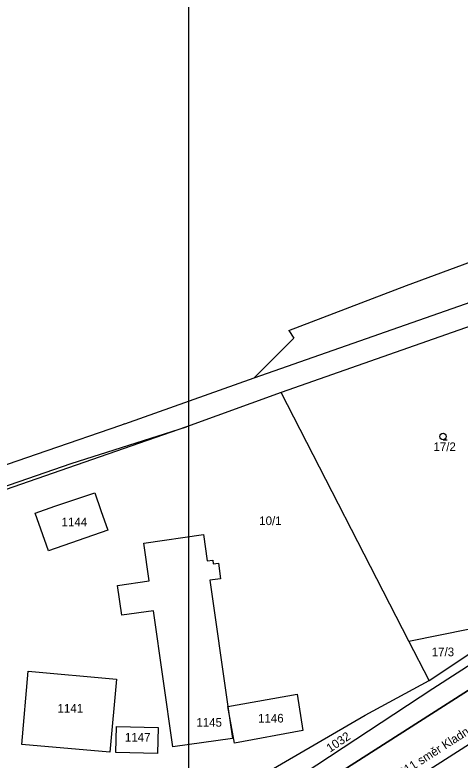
# Model space of a CAD drawing. Extents: x -752184 to -751416, y -1028299 to -1027836.
# Drawn here: x -751921.2 to -751817.9, y -1028131.4 to -1027958.6 of the extents above; entities that cross this region are included whole.
import ezdxf

# ---------------------------------------------------------------- set-up
doc = ezdxf.new("R2010")
doc.units = 0
for name, color, linetype in [('02_Osa_koleje', 7, 'Continuous'), ('Vrstva 4', 7, 'Continuous'), ('Vrstva 53', 7, 'Continuous'), ('Vrstva 55', 7, 'Continuous'), ('Vrstva 57', 7, 'Continuous'), ('Vrstva 58', 7, 'Continuous'), ('Vrstva 63', 7, 'Continuous')]:
    doc.layers.add(name, color=color, linetype=linetype)

msp = doc.modelspace()

# ---------------------------------------------------------------- linework, layer by layer
at = {"layer": 'Vrstva 4'}
msp.add_lwpolyline([(-751880.79, -1027897.6), (-751466.79, -1027897.6), (-751466.79, -1028188.6), (-751880.79, -1028188.6)], close=True, dxfattribs=at)
at = {"layer": 'Vrstva 53'}
msp.add_lwpolyline([(-751934.1, -1028186.19), (-751914.9, -1028176.41), (-751903.43, -1028170.23), (-751901.96, -1028169.44), (-751904.77, -1028166.14), (-751893.52, -1028163.47), (-751890.97, -1028163.13), (-751806.75, -1028109.29), (-751808.53, -1028106.05), (-751798.29, -1028099.68), (-751750.57, -1028069.21), (-751709.61, -1028036.63), (-751702.85, -1028029.39), (-751690.7, -1028035.11), (-751634.83, -1027999.42), (-751532.07, -1027933.64), (-751519.82, -1027926.47), (-751506.87, -1027919.58), (-751494.13, -1027913.25), (-751481.54, -1027906.54), (-751469.19, -1027899.14), (-751466.79, -1027897.6)], dxfattribs=at)
at = {"layer": 'Vrstva 55'}
for p, q in [((-751830.33, -1028021.31), (-751777.61, -1028001.77)), ((-751857.65, -1028031.73), (-751830.33, -1028021.31)), ((-751803.99, -1028026.65), (-751859.41, -1028046.14)), ((-751895.64, -1028053.38), (-751865.7, -1028042.71)), ((-751859.41, -1028046.14), (-751881.38, -1028054.14)), ((-751829.79, -1028103.79), (-751859.41, -1028046.14)), ((-751881.38, -1028054.14), (-752003.38, -1028096.4)), ((-751896.64, -1028053.77), (-751913.74, -1028059.67)), ((-751895.64, -1028053.38), (-751896.64, -1028053.77)), ((-751913.74, -1028059.67), (-751933.45, -1028066.43)), ((-751825.11, -1028112.91), (-751790.46, -1028089.89)), ((-751825.11, -1028112.91), (-751829.79, -1028103.79))]:
    msp.add_line(p, q, dxfattribs=at)
for points in [[(-751865.7, -1028042.71), (-751749.56, -1028002.08), (-751713.49, -1027990.7), (-751668.79, -1027968.97)], [(-751857.65, -1028031.73), (-751856.49, -1028033.54), (-751865.7, -1028042.71)], [(-752003.56, -1028095.62), (-751908.15, -1028062.63), (-751881.38, -1028054.14)], [(-751884.03, -1028148.84), (-751854.09, -1028134.41), (-751824.25, -1028114.78), (-751751.51, -1028067.92)], [(-751902.66, -1028069.39), (-751901.2, -1028073.54), (-751899.62, -1028078.07), (-751913.4, -1028082.89), (-751916.47, -1028074.11), (-751911.88, -1028072.54), (-751902.66, -1028069.39)], [(-751750.57, -1028069.21), (-751798.29, -1028099.68), (-751808.53, -1028106.05), (-751806.75, -1028109.29), (-751890.97, -1028163.13), (-751893.52, -1028163.47)], [(-751871.76, -1028119), (-751870.71, -1028126.36), (-751884.51, -1028128.34), (-751889.05, -1028096.75), (-751896.33, -1028097.8), (-751897.36, -1028090.88), (-751890.04, -1028089.83), (-751891.29, -1028081.06), (-751877.43, -1028079.08), (-751876.57, -1028085.19), (-751875.28, -1028085.01), (-751875.15, -1028085.9), (-751873.96, -1028085.73), (-751873.45, -1028089.34), (-751875.93, -1028089.7), (-751871.76, -1028119)], [(-751829.79, -1028103.79), (-751815.64, -1028100.96), (-751805.78, -1028097.41), (-751790.88, -1028089.26), (-751790.46, -1028089.89)], [(-751897.63, -1028112.6), (-751899.12, -1028129.53), (-751919.55, -1028127.76), (-751918.08, -1028110.8), (-751897.63, -1028112.6)], [(-751886.38, -1028143.87), (-751862.7, -1028134.19), (-751839.92, -1028121.01), (-751825.11, -1028112.91)], [(-751871.76, -1028119), (-751855.74, -1028116.09), (-751854.37, -1028124.51), (-751870.23, -1028127.46), (-751871.76, -1028119)], [(-751897.58, -1028123.64), (-751887.96, -1028123.82), (-751888.1, -1028129.87), (-751897.72, -1028129.64), (-751897.58, -1028123.64)]]:
    msp.add_lwpolyline(points, dxfattribs=at)
at = {"layer": 'Vrstva 58'}
msp.add_line((-751821.89, -1028057.08), (-751820.89, -1028057.08), dxfattribs=at)
msp.add_circle((-751821.89, -1028056.33), 0.75, dxfattribs=at)
at = {"layer": 'Vrstva 63'}
msp.add_line((-751551.77, -1027958.95), (-751975.84, -1028230), dxfattribs=at)

# ---------------------------------------------------------------- texts
at = {"layer": '02_Osa_koleje'}
msp.add_text('TÚ 0811 směr Kladno', height=2, rotation=32.6028, dxfattribs=at).set_placement((-751836.27, -1028138.5))
at = {"layer": 'Vrstva 57'}
for s, p in [('17/2', (-751824.11, -1028059.72)), ('1144', (-751910.34, -1028077.17)), ('10/1', (-751864.51, -1028076.89)), ('17/3', (-751824.52, -1028107.3)), ('1141', (-751911.28, -1028120.38)), ('1145', (-751879.09, -1028123.65)), ('1146', (-751864.79, -1028122.68)), ('1147', (-751895.65, -1028127.09))]:
    msp.add_text(s, height=2, dxfattribs=at).set_placement(p)
msp.add_text('1032', height=2, rotation=34, dxfattribs=at).set_placement((-751848.08, -1028129.69))

doc.saveas('drawing.dxf')
